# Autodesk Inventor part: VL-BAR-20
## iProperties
Created: 2005-08
Part Number: VL-BAR-20
Document SubType Name: Sheet Metal
Density: 1 g/cm^3
Mass: 3.38147 g
Surface Area: 65.3758 cm^2
Volume: 3.38147 cm^3
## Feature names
1. Rectangular Pattern1
2. Plate1
